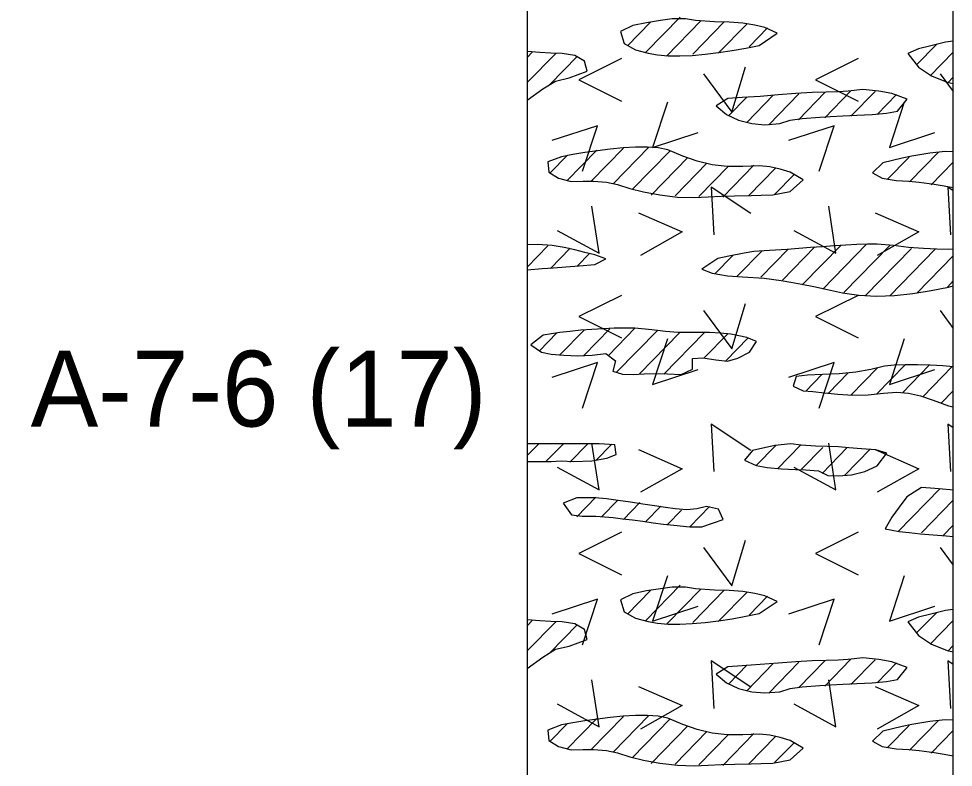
# Model space of a CAD drawing. Extents: x -0.01 to 0.83, y -0.63 to 1.27.
# Drawn here: x 0.7511 to 0.8333, y 0.7201 to 0.7859 of the extents above; entities that cross this region are included whole.
import ezdxf

# ---------------------------------------------------------------- set-up
doc = ezdxf.new("R2010")
doc.units = 0

msp = doc.modelspace()

# ---------------------------------------------------------------- linework, layer by layer
for points in [[(0, 0), (0.833332, 0), (0.833332, 1.274997), (0, 1.274997)], [(0, 0), (0.833332, 0), (0.833332, 1.274997), (0, 1.274997)], [(0, 0), (0.833332, 0), (0.833332, 1.274997), (0, 1.274997)], [(0, 0), (0.833332, 0), (0.833332, 1.274997), (0, 1.274997)], [(0, 0), (0.833332, 0), (0.833332, 1.274997), (0, 1.274997)], [(0.812326, 0.785653), (0.810635, 0.785772), (0.809773, 0.785906), (0.808601, 0.785913), (0.807553, 0.785769), (0.806321, 0.78557), (0.805133, 0.785326), (0.804031, 0.784805), (0.804359, 0.783745), (0.805363, 0.783177), (0.806466, 0.78288), (0.807303, 0.782729), (0.80824, 0.782653), (0.80926, 0.782644), (0.810349, 0.782694), (0.811489, 0.782797), (0.812666, 0.782944), (0.813863, 0.783128), (0.815063, 0.783341), (0.816252, 0.783575), (0.81783, 0.784656), (0.816735, 0.785155), (0.815852, 0.785357), (0.814797, 0.785515), (0.813609, 0.785617)], [(0.832654, 0.783841), (0.831362, 0.783532), (0.830275, 0.783257), (0.829339, 0.782863), (0.830265, 0.781663), (0.831418, 0.7809), (0.832792, 0.780322), (0.833332, 0.780223), (0.833332, 0.783931)], [(0.795832, 0.778745), (0.79719, 0.779735), (0.798312, 0.780436), (0.799509, 0.780707), (0.801112, 0.781309), (0.800861, 0.782193), (0.800021, 0.782668), (0.798893, 0.782863), (0.797908, 0.782893), (0.796943, 0.78295), (0.795832, 0.783032)], [(0.825375, 0.779688), (0.824078, 0.779538), (0.823187, 0.779481), (0.822142, 0.779457), (0.820907, 0.77942), (0.819474, 0.779327), (0.817918, 0.779207), (0.816318, 0.779087), (0.814751, 0.778995), (0.813476, 0.778894), (0.812472, 0.778254), (0.813366, 0.777494), (0.814436, 0.776989), (0.815612, 0.776701), (0.816749, 0.776596), (0.818067, 0.776708), (0.818959, 0.776984), (0.820031, 0.777128), (0.821573, 0.77725), (0.82253, 0.777308), (0.823615, 0.777366), (0.824832, 0.777427), (0.826183, 0.777494), (0.827451, 0.777602), (0.828416, 0.777777), (0.829268, 0.778832), (0.827909, 0.779349), (0.826788, 0.779548)], [(0.798854, 0.773779), (0.797634, 0.773318), (0.797728, 0.772422), (0.798587, 0.771899), (0.799696, 0.771603), (0.800742, 0.771613), (0.801652, 0.771627), (0.802809, 0.771543), (0.803766, 0.771336), (0.804856, 0.770986), (0.80606, 0.77069), (0.807509, 0.770416), (0.809046, 0.77023), (0.810517, 0.770199), (0.811769, 0.770257), (0.812889, 0.770297), (0.814075, 0.770332), (0.815527, 0.770373), (0.816416, 0.770399), (0.817445, 0.77043), (0.818967, 0.770704), (0.820111, 0.77174), (0.818963, 0.772409), (0.818099, 0.772676), (0.817169, 0.772872), (0.816265, 0.772977), (0.814793, 0.772919), (0.813435, 0.772922), (0.812104, 0.773072), (0.810802, 0.773374), (0.809527, 0.773834), (0.808198, 0.774384), (0.807356, 0.774544), (0.806403, 0.774618), (0.805364, 0.774619), (0.804267, 0.774558), (0.803138, 0.77445), (0.802006, 0.774305), (0.800896, 0.774137), (0.799837, 0.773957)], [(0.832629, 0.774225), (0.831261, 0.774088), (0.829688, 0.773822), (0.828826, 0.773649), (0.82712, 0.773238), (0.826226, 0.772369), (0.827084, 0.771878), (0.828308, 0.771691), (0.829408, 0.771626), (0.830335, 0.771537), (0.831655, 0.771354), (0.832526, 0.771212), (0.833332, 0.77107), (0.833332, 0.774218)], [(0.795832, 0.763822), (0.797147, 0.763932), (0.798141, 0.764005), (0.799224, 0.764083), (0.800394, 0.764168), (0.80179, 0.76429), (0.802748, 0.764804), (0.801793, 0.765146), (0.800911, 0.76536), (0.800027, 0.765581), (0.79909, 0.765787), (0.798029, 0.765953), (0.79677, 0.766048), (0.795832, 0.766028)], [(0.828162, 0.761574), (0.82978, 0.761744), (0.831374, 0.761996), (0.832902, 0.762307), (0.833332, 0.762412), (0.833332, 0.765652), (0.832951, 0.765619), (0.831885, 0.765641), (0.830714, 0.765694), (0.829383, 0.765796), (0.828069, 0.765965), (0.826619, 0.766084), (0.825765, 0.766087), (0.824843, 0.766059), (0.823868, 0.766009), (0.822856, 0.76594), (0.82182, 0.765861), (0.820774, 0.765777), (0.819735, 0.765694), (0.818715, 0.765619), (0.817148, 0.765524), (0.815785, 0.765431), (0.814914, 0.765298), (0.813574, 0.765023), (0.812595, 0.76481), (0.811206, 0.763892), (0.812105, 0.76353), (0.813452, 0.763284), (0.814789, 0.763194), (0.816678, 0.763091), (0.818181, 0.762891), (0.819046, 0.762745), (0.820004, 0.762566), (0.821067, 0.762351), (0.82225, 0.7621), (0.823565, 0.761808), (0.825013, 0.761582), (0.826559, 0.761513)], [(0.797084, 0.756593), (0.797938, 0.756415), (0.799042, 0.756303), (0.800285, 0.756269), (0.801555, 0.756323), (0.802742, 0.756477), (0.803614, 0.755816), (0.803377, 0.754919), (0.804221, 0.754648), (0.805167, 0.75463), (0.806129, 0.754685), (0.807202, 0.754716), (0.808182, 0.754685), (0.809387, 0.754612), (0.81037, 0.755078), (0.81038, 0.756025), (0.811296, 0.756087), (0.812442, 0.7559), (0.813463, 0.755794), (0.814379, 0.75605), (0.815394, 0.756592), (0.816006, 0.757505), (0.81517, 0.757878), (0.813738, 0.758154), (0.812849, 0.758247), (0.811872, 0.758305), (0.810001, 0.758307), (0.809104, 0.758325), (0.808002, 0.758399), (0.806784, 0.758556), (0.805305, 0.758686), (0.804427, 0.758699), (0.803488, 0.758683), (0.802511, 0.758643), (0.801521, 0.758581), (0.80054, 0.758503), (0.799593, 0.758412), (0.798702, 0.758313), (0.797221, 0.758089), (0.796138, 0.757212)], [(0.832407, 0.755374), (0.831293, 0.755438), (0.830172, 0.755475), (0.829096, 0.755477), (0.828115, 0.755438), (0.827281, 0.75535), (0.826083, 0.755051), (0.824762, 0.754825), (0.823296, 0.754688), (0.821831, 0.754606), (0.820509, 0.754546), (0.819505, 0.754448), (0.819224, 0.753583), (0.820125, 0.753164), (0.820967, 0.753113), (0.821997, 0.753013), (0.823181, 0.752883), (0.824476, 0.752795), (0.825838, 0.75282), (0.82719, 0.752984), (0.828356, 0.753051), (0.829402, 0.75297), (0.830435, 0.752737), (0.831559, 0.752346), (0.832909, 0.751856), (0.833332, 0.75178), (0.833332, 0.755299)], [(0.795832, 0.746961), (0.796757, 0.746951), (0.797925, 0.74697), (0.798816, 0.747009), (0.799915, 0.746966), (0.801515, 0.74701), (0.802823, 0.747266), (0.803666, 0.747586), (0.80354, 0.748425), (0.802165, 0.74851), (0.795832, 0.74851)], [(0.818216, 0.746316), (0.819444, 0.746257), (0.820325, 0.746217), (0.821453, 0.746149), (0.822286, 0.745735), (0.82324, 0.745691), (0.824378, 0.745796), (0.825554, 0.746084), (0.826624, 0.746589), (0.82749, 0.747686), (0.826513, 0.747989), (0.825239, 0.74809), (0.82413, 0.748154), (0.823236, 0.74826), (0.822257, 0.748279), (0.821211, 0.748303), (0.819948, 0.748394), (0.819024, 0.74851), (0.817611, 0.74837), (0.815663, 0.747927), (0.814958, 0.747088), (0.815983, 0.746599), (0.816947, 0.746424)], [(0.833053, 0.744462), (0.831709, 0.744574), (0.830539, 0.744675), (0.829246, 0.743855), (0.828567, 0.742941), (0.827924, 0.742054), (0.827345, 0.741027), (0.828579, 0.740802), (0.829451, 0.740701), (0.830451, 0.740604), (0.831549, 0.740509), (0.832716, 0.740412), (0.833332, 0.740361), (0.833332, 0.744453)], [(0.800664, 0.742159), (0.801881, 0.742152), (0.803392, 0.742024), (0.804229, 0.741928), (0.805103, 0.741818), (0.806004, 0.7417), (0.806919, 0.741579), (0.807838, 0.74146), (0.808747, 0.74135), (0.810142, 0.741209), (0.811186, 0.741221), (0.812223, 0.741566), (0.81308, 0.741851), (0.812673, 0.742753), (0.811597, 0.743), (0.810749, 0.742802), (0.809892, 0.742719), (0.808847, 0.7428), (0.807995, 0.742911), (0.807033, 0.743055), (0.805997, 0.743218), (0.804922, 0.743386), (0.803843, 0.743543), (0.802797, 0.743675), (0.801817, 0.743767), (0.800202, 0.743775), (0.799007, 0.743303), (0.79974, 0.74226)], [(0.812326, 0.735653), (0.810635, 0.735772), (0.809773, 0.735906), (0.808601, 0.735913), (0.807553, 0.735769), (0.806321, 0.73557), (0.805133, 0.735326), (0.804031, 0.734805), (0.804359, 0.733745), (0.805363, 0.733178), (0.806466, 0.73288), (0.807303, 0.732729), (0.80824, 0.732653), (0.80926, 0.732644), (0.810349, 0.732695), (0.811489, 0.732797), (0.812666, 0.732944), (0.813863, 0.733128), (0.815063, 0.733341), (0.816252, 0.733575), (0.81783, 0.734656), (0.816735, 0.735155), (0.815852, 0.735357), (0.814797, 0.735515), (0.813609, 0.735617)], [(0.832654, 0.733841), (0.831362, 0.733532), (0.830275, 0.733257), (0.829339, 0.732863), (0.830265, 0.731663), (0.831418, 0.7309), (0.832792, 0.730322), (0.833332, 0.730223), (0.833332, 0.733931)], [(0.795832, 0.728745), (0.79719, 0.729735), (0.798312, 0.730436), (0.799509, 0.730708), (0.801112, 0.731309), (0.800861, 0.732193), (0.800021, 0.732669), (0.798893, 0.732863), (0.797908, 0.732893), (0.796943, 0.73295), (0.795832, 0.733032)], [(0.825375, 0.729688), (0.824078, 0.729538), (0.823187, 0.729481), (0.822142, 0.729457), (0.820907, 0.72942), (0.819474, 0.729327), (0.817918, 0.729207), (0.816318, 0.729087), (0.814751, 0.728995), (0.813476, 0.728894), (0.812472, 0.728254), (0.813366, 0.727494), (0.814436, 0.726989), (0.815612, 0.726701), (0.816749, 0.726596), (0.818067, 0.726708), (0.818959, 0.726984), (0.820031, 0.727128), (0.821573, 0.72725), (0.82253, 0.727308), (0.823615, 0.727366), (0.824832, 0.727428), (0.826183, 0.727494), (0.827451, 0.727602), (0.828416, 0.727777), (0.829268, 0.728832), (0.827909, 0.729349), (0.826788, 0.729548)], [(0.798854, 0.723779), (0.797634, 0.723318), (0.797728, 0.722422), (0.798587, 0.721899), (0.799696, 0.721603), (0.800742, 0.721613), (0.801652, 0.721627), (0.802809, 0.721544), (0.803766, 0.721336), (0.804856, 0.720987), (0.80606, 0.72069), (0.807509, 0.720416), (0.809046, 0.72023), (0.810517, 0.720199), (0.811769, 0.720257), (0.812889, 0.720297), (0.814075, 0.720333), (0.815527, 0.720373), (0.816416, 0.720399), (0.817445, 0.72043), (0.818967, 0.720704), (0.820111, 0.72174), (0.818963, 0.722409), (0.818099, 0.722676), (0.817169, 0.722873), (0.816265, 0.722977), (0.814793, 0.722919), (0.813435, 0.722922), (0.812104, 0.723072), (0.810802, 0.723374), (0.809527, 0.723834), (0.808198, 0.724384), (0.807356, 0.724544), (0.806403, 0.724618), (0.805364, 0.724619), (0.804267, 0.724559), (0.803138, 0.72445), (0.802006, 0.724305), (0.800896, 0.724137), (0.799837, 0.723957)], [(0.832629, 0.724225), (0.831261, 0.724088), (0.829688, 0.723823), (0.828826, 0.723649), (0.82712, 0.723238), (0.826226, 0.72237), (0.827084, 0.721878), (0.828308, 0.721691), (0.829408, 0.721626), (0.830335, 0.721537), (0.831655, 0.721354), (0.832526, 0.721212), (0.833332, 0.72107), (0.833332, 0.724218)]]:
    msp.add_lwpolyline(points, close=True)
for points in [[(0.795832, 1.220831), (0.795832, -0.621832)], [(0.833332, -0.621832), (0.833332, 1.138431)], [(0.804649, 0.783537), (0.806674, 0.785611)], [(0.806256, 0.78297), (0.809278, 0.786067)], [(0.80809, 0.782637), (0.811113, 0.785734)], [(0.810409, 0.782801), (0.813175, 0.785635)], [(0.812643, 0.782877), (0.815181, 0.785477)], [(0.815361, 0.783449), (0.816987, 0.785114)], [(0.830098, 0.781874), (0.831838, 0.783657)], [(0.796303, 0.782991), (0.795832, 0.782507)], [(0.798338, 0.782863), (0.795832, 0.780295)], [(0.797862, 0.780163), (0.800229, 0.782588)], [(0.804125, 0.782413), (0.800375, 0.780538), (0.804125, 0.778663)], [(0.824958, 0.782413), (0.821208, 0.780538), (0.824958, 0.778663)], [(0.831305, 0.7809), (0.833332, 0.782976)], [(0.811342, 0.781072), (0.813842, 0.777697), (0.815029, 0.781697)], [(0.832175, 0.781072), (0.833332, 0.779511)], [(0.832854, 0.780273), (0.833332, 0.780762)], [(0.815192, 0.779058), (0.813538, 0.777363)], [(0.815145, 0.776797), (0.817482, 0.779191)], [(0.817092, 0.776579), (0.819744, 0.779296)], [(0.819696, 0.777034), (0.822034, 0.779431)], [(0.822015, 0.777198), (0.824297, 0.779536)], [(0.824306, 0.777333), (0.826445, 0.779525)], [(0.826625, 0.777497), (0.828336, 0.77925)], [(0.808181, 0.778582), (0.806868, 0.774582), (0.810868, 0.775894)], [(0.829014, 0.778582), (0.827702, 0.774582), (0.831702, 0.775894)], [(0.800689, 0.772501), (0.802002, 0.776501), (0.798002, 0.775189)], [(0.821523, 0.772501), (0.822835, 0.776501), (0.818835, 0.775189)], [(0.799328, 0.771653), (0.801951, 0.774341)], [(0.801419, 0.771582), (0.804299, 0.774534)], [(0.806532, 0.77461), (0.803395, 0.771395)], [(0.805059, 0.770887), (0.808397, 0.774307)], [(0.832025, 0.774174), (0.829489, 0.771574)], [(0.799375, 0.773915), (0.797863, 0.772365)], [(0.809973, 0.77371), (0.806747, 0.770404)], [(0.827512, 0.771761), (0.82945, 0.773747)], [(0.831379, 0.771299), (0.833332, 0.7733)], [(0.811636, 0.773202), (0.808841, 0.770338)], [(0.813527, 0.772926), (0.810936, 0.770272)], [(0.813032, 0.770206), (0.815789, 0.773032)], [(0.815342, 0.77036), (0.817681, 0.772757)], [(0.817605, 0.770466), (0.819344, 0.772249)], [(0.815512, 0.768775), (0.812012, 0.771088), (0.812262, 0.7669)], [(0.833332, 0.770766), (0.832845, 0.771088), (0.833095, 0.7669)], [(0.833327, 0.771083), (0.833332, 0.771088)], [(0.798466, 0.767293), (0.802154, 0.765293), (0.801529, 0.769418)], [(0.8193, 0.767293), (0.822987, 0.765293), (0.822362, 0.769418)], [(0.805617, 0.768838), (0.809456, 0.767154), (0.805806, 0.765093)], [(0.82645, 0.768838), (0.83029, 0.767154), (0.826639, 0.765093)], [(0.797655, 0.765935), (0.795832, 0.764067)], [(0.820035, 0.762495), (0.823455, 0.765999)], [(0.825691, 0.766077), (0.82184, 0.762132)], [(0.827752, 0.765976), (0.823702, 0.761828)], [(0.799604, 0.765719), (0.797864, 0.763937)], [(0.801295, 0.76524), (0.800268, 0.764188)], [(0.813923, 0.765083), (0.812354, 0.763476)], [(0.814303, 0.76326), (0.816499, 0.765509)], [(0.816395, 0.76319), (0.818789, 0.765644)], [(0.818285, 0.762915), (0.821137, 0.765837)], [(0.829644, 0.765702), (0.825565, 0.761524)], [(0.831735, 0.765633), (0.827743, 0.761542)], [(0.833332, 0.765055), (0.830118, 0.761763)], [(0.832808, 0.762307), (0.833332, 0.762843)], [(0.804125, 0.76158), (0.800375, 0.759705), (0.804125, 0.75783)], [(0.824958, 0.76158), (0.821208, 0.759705), (0.824958, 0.75783)], [(0.811342, 0.760239), (0.813842, 0.756864), (0.815029, 0.760864)], [(0.832175, 0.760239), (0.833332, 0.758677)], [(0.79871, 0.756336), (0.800849, 0.758527)], [(0.800827, 0.756292), (0.803111, 0.758632)], [(0.805344, 0.758707), (0.802987, 0.756292)], [(0.80367, 0.75478), (0.807321, 0.75852)], [(0.798444, 0.758276), (0.796912, 0.756706)], [(0.805714, 0.754661), (0.809241, 0.758275)], [(0.808181, 0.757748), (0.806868, 0.753748), (0.810868, 0.755061)], [(0.811418, 0.758293), (0.807854, 0.75464)], [(0.811407, 0.756069), (0.81348, 0.758194)], [(0.815282, 0.757827), (0.813313, 0.75581)], [(0.829014, 0.757748), (0.827702, 0.753748), (0.831702, 0.755061)], [(0.800689, 0.751668), (0.802002, 0.755668), (0.798002, 0.754355)], [(0.821523, 0.751668), (0.822835, 0.755668), (0.818835, 0.754355)], [(0.824327, 0.752805), (0.82666, 0.755195)], [(0.829094, 0.755477), (0.826565, 0.752885)], [(0.828848, 0.753013), (0.831218, 0.755441)], [(0.833245, 0.755306), (0.830651, 0.752647)], [(0.820346, 0.753151), (0.821763, 0.754603)], [(0.822335, 0.752976), (0.824076, 0.754761)], [(0.833332, 0.753181), (0.832267, 0.752089)], [(0.815512, 0.747942), (0.812012, 0.750254), (0.812262, 0.746067)], [(0.833332, 0.749933), (0.832845, 0.750254), (0.833095, 0.746067)], [(0.798466, 0.746459), (0.802154, 0.744459), (0.801529, 0.748584)], [(0.8193, 0.746459), (0.822987, 0.744459), (0.822362, 0.748584)], [(0.795832, 0.74748), (0.796808, 0.74848)], [(0.798985, 0.748498), (0.797473, 0.746949)], [(0.801161, 0.748515), (0.799593, 0.746908)], [(0.803281, 0.748475), (0.801883, 0.747043)], [(0.805617, 0.748005), (0.809456, 0.746321), (0.805806, 0.744259)], [(0.817701, 0.748374), (0.815961, 0.74659)], [(0.819878, 0.748391), (0.817852, 0.746315)], [(0.821854, 0.748203), (0.819972, 0.746274)], [(0.824002, 0.748191), (0.821778, 0.745912)], [(0.826007, 0.748033), (0.823783, 0.745754)], [(0.82645, 0.748005), (0.83029, 0.746321), (0.826639, 0.744259)], [(0.832167, 0.744588), (0.828441, 0.74077)], [(0.801877, 0.743814), (0.800195, 0.742091)], [(0.803798, 0.74357), (0.80237, 0.742107)], [(0.805745, 0.743353), (0.804291, 0.741862)], [(0.80758, 0.74302), (0.806268, 0.741675)], [(0.811876, 0.742997), (0.810165, 0.741243)], [(0.833332, 0.743569), (0.830521, 0.740689)], [(0.809414, 0.742687), (0.808159, 0.741401)], [(0.833332, 0.741356), (0.832451, 0.740453)], [(0.804125, 0.740747), (0.800375, 0.738872), (0.804125, 0.736997)], [(0.824958, 0.740747), (0.821208, 0.738872), (0.824958, 0.736997)], [(0.811342, 0.739406), (0.813842, 0.736031), (0.815029, 0.740031)], [(0.832175, 0.739406), (0.833332, 0.737844)], [(0.808181, 0.736915), (0.806868, 0.732915), (0.810868, 0.734228)], [(0.829014, 0.736915), (0.827702, 0.732915), (0.831702, 0.734228)], [(0.804649, 0.733537), (0.806674, 0.735612)], [(0.806256, 0.73297), (0.809278, 0.736067)], [(0.80809, 0.732637), (0.811113, 0.735734)], [(0.810409, 0.732801), (0.813175, 0.735635)], [(0.812643, 0.732877), (0.815181, 0.735477)], [(0.800689, 0.730835), (0.802002, 0.734835), (0.798002, 0.733522)], [(0.815361, 0.733449), (0.816987, 0.735114)], [(0.821523, 0.730835), (0.822835, 0.734835), (0.818835, 0.733522)], [(0.796303, 0.732991), (0.795832, 0.732507)], [(0.830098, 0.731874), (0.831838, 0.733657)], [(0.831305, 0.7309), (0.833332, 0.732976)], [(0.798338, 0.732863), (0.795832, 0.730295)], [(0.797862, 0.730163), (0.800229, 0.732588)], [(0.832854, 0.730274), (0.833332, 0.730763)], [(0.815512, 0.727109), (0.812012, 0.729421), (0.812262, 0.725234)], [(0.815192, 0.729058), (0.813538, 0.727363)], [(0.815145, 0.726797), (0.817482, 0.729192)], [(0.817092, 0.726579), (0.819744, 0.729296)], [(0.819696, 0.727034), (0.822034, 0.729431)], [(0.822015, 0.727198), (0.824297, 0.729536)], [(0.824306, 0.727333), (0.826445, 0.729525)], [(0.826625, 0.727497), (0.828336, 0.72925)], [(0.833332, 0.7291), (0.832845, 0.729421), (0.833095, 0.725234)], [(0.798466, 0.725626), (0.802154, 0.723626), (0.801529, 0.727751)], [(0.8193, 0.725626), (0.822987, 0.723626), (0.822362, 0.727751)], [(0.805617, 0.727171), (0.809456, 0.725488), (0.805806, 0.723426)], [(0.82645, 0.727171), (0.83029, 0.725488), (0.826639, 0.723426)], [(0.799375, 0.723915), (0.797863, 0.722365)], [(0.799328, 0.721653), (0.801951, 0.724341)], [(0.801419, 0.721582), (0.804299, 0.724534)], [(0.806532, 0.72461), (0.803395, 0.721395)], [(0.805059, 0.720887), (0.808397, 0.724307)], [(0.832025, 0.724174), (0.829489, 0.721574)], [(0.809973, 0.72371), (0.806747, 0.720404)], [(0.811636, 0.723202), (0.808841, 0.720338)], [(0.827512, 0.721762), (0.82945, 0.723747)], [(0.831379, 0.721299), (0.833332, 0.7233)], [(0.813527, 0.722926), (0.810936, 0.720272)], [(0.813032, 0.720206), (0.815789, 0.723032)], [(0.815342, 0.72036), (0.817681, 0.722757)], [(0.817605, 0.720466), (0.819344, 0.722249)], [(0.833327, 0.721083), (0.833332, 0.721088)]]:
    msp.add_lwpolyline(points)

# ---------------------------------------------------------------- texts
msp.add_text('A-7-6 (17)', height=0.0066667).set_placement((0.752128, 0.75004))

doc.saveas('drawing.dxf')
